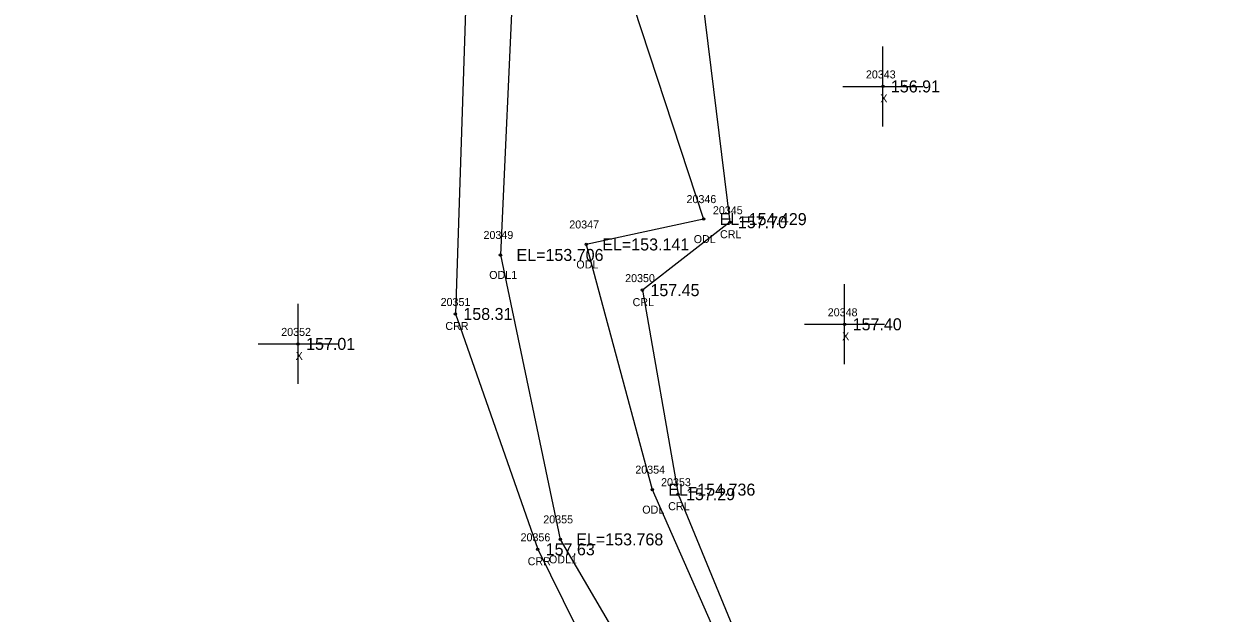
# Model space of a CAD drawing. Extents: x 2381545 to 2382928, y 1029933 to 1030589.
# Drawn here: x 2382160.7 to 2382309.6, y 1030240.2 to 1030313.9 of the extents above; entities that cross this region are included whole.
import ezdxf

# ---------------------------------------------------------------- set-up
doc = ezdxf.new("R2010")
doc.units = 0
for name, color, linetype in [('RD_EX_H2O', 7, 'Continuous'), ('RD_EX_H2O_txCode', 7, 'Continuous'), ('RD_EX_Misc', 7, 'Continuous'), ('RD_EX_Misc_txCode', 7, 'Continuous'), ('RD_EX_TX_H2O_ELEV', 7, 'Continuous'), ('RD_EX_TX_Misc_ELEV', 7, 'Continuous'), ('RD_SMD_Locator', 7, 'Continuous')]:
    doc.layers.add(name, color=color, linetype=linetype)

msp = doc.modelspace()

# ---------------------------------------------------------------- linework, layer by layer
at = {"layer": 'RD_EX_H2O'}
for points in [[(2382228.76, 1030407.08), (2382229.33, 1030393.42), (2382229.44, 1030376.02), (2382235.1, 1030355.5), (2382240.51, 1030349.49), (2382245.56, 1030316.86), (2382248.97, 1030289.05), (2382238.04, 1030280.56), (2382242.49, 1030255.05), (2382259.38, 1030214.05), (2382335.14, 1030213.97), (2382351.43, 1030124.97), (2382330.65, 1030084.53), (2382333.22, 1030050.31), (2382344.99, 1030019.27), (2382333.68, 1029961.92)], [(2382160.73, 1030399.39), (2382197.66, 1030393.98), (2382201.16, 1030391.22), (2382207.75, 1030374.4), (2382216.83, 1030343.34), (2382214.66, 1030277.58), (2382224.95, 1030248.16), (2382253.35, 1030190.66), (2382280.97, 1030189.84), (2382308.61, 1030179.94), (2382336.27, 1030122.7), (2382320.51, 1030086.69), (2382321.43, 1030050.4), (2382332.53, 1030017.35), (2382333.68, 1029961.92)], [(2382220.88, 1030388.74), (2382227.06, 1030360.93), (2382229.81, 1030345.11), (2382235.02, 1030321.93), (2382245.69, 1030289.44), (2382231.02, 1030286.27), (2382239.27, 1030255.62), (2382259.54, 1030209.53), (2382328.62, 1030208.08), (2382346.92, 1030124.75), (2382326.86, 1030085.52), (2382331.57, 1030050.13), (2382343.53, 1030018.97), (2382333.68, 1029961.92)], [(2382213.26, 1030387.6), (2382221.81, 1030359.48), (2382223.97, 1030346.38), (2382221.92, 1030320.69), (2382220.3, 1030284.96), (2382227.77, 1030249.4), (2382256.92, 1030199.53), (2382280.94, 1030192.97), (2382312.22, 1030183.5), (2382338.65, 1030122.69), (2382323.29, 1030086.32), (2382328.28, 1030050.33), (2382335.32, 1030017.57), (2382333.68, 1029961.92)]]:
    msp.add_lwpolyline(points, dxfattribs=at)
at = {"layer": 'RD_EX_Misc'}
for p, q in [((2382268.09, 1030301.03), (2382268.09, 1030311.03)), ((2382263.09, 1030306.03), (2382273.09, 1030306.03)), ((2382263.31, 1030271.29), (2382263.31, 1030281.29)), ((2382195.01, 1030268.84), (2382195.01, 1030278.84)), ((2382258.31, 1030276.29), (2382268.31, 1030276.29)), ((2382190.01, 1030273.84), (2382200.01, 1030273.84))]:
    msp.add_line(p, q, dxfattribs=at)
at = {"layer": 'RD_SMD_Locator'}
for centre in [(2382268.09, 1030306.03), (2382245.69, 1030289.44), (2382248.97, 1030289.05), (2382220.3, 1030284.96), (2382231.02, 1030286.27), (2382238.04, 1030280.56), (2382214.66, 1030277.58), (2382263.31, 1030276.29), (2382195.01, 1030273.84), (2382239.27, 1030255.62), (2382242.49, 1030255.05), (2382227.77, 1030249.4), (2382224.95, 1030248.16)]:
    msp.add_circle(centre, 0.15, dxfattribs=at)

# ---------------------------------------------------------------- texts
at = {"layer": 'RD_EX_H2O_txCode'}
for s, p in [('20346', (2382243.55, 1030291.44)), ('20345', (2382246.85, 1030290.05)), ('20349', (2382218.18, 1030286.96)), ('20347', (2382228.9, 1030288.27)), ('CRL', (2382247.74, 1030287.05)), ('ODL', (2382244.45, 1030286.44)), ('ODL', (2382229.78, 1030283.27)), ('ODL1', (2382218.89, 1030281.96)), ('20350', (2382235.88, 1030281.56)), ('20351', (2382212.82, 1030278.58)), ('CRL', (2382236.81, 1030278.56)), ('CRR', (2382213.41, 1030275.58)), ('20354', (2382237.15, 1030257.62)), ('20353', (2382240.37, 1030256.05)), ('CRL', (2382241.26, 1030253.05)), ('20355', (2382225.65, 1030251.4)), ('ODL', (2382238.02, 1030252.62)), ('20356', (2382222.81, 1030249.16)), ('CRR', (2382223.7, 1030246.16)), ('ODL1', (2382226.36, 1030246.4))]:
    msp.add_text(s, height=1, dxfattribs=at).set_placement(p)
at = {"layer": 'RD_EX_Misc_txCode'}
for s, p in [('20343', (2382265.97, 1030307.03)), ('X', (2382267.77, 1030304.03)), ('20348', (2382261.2, 1030277.29)), ('20352', (2382192.9, 1030274.84)), ('X', (2382263, 1030274.29)), ('X', (2382194.7, 1030271.84))]:
    msp.add_text(s, height=1, dxfattribs=at).set_placement(p)
at = {"layer": 'RD_EX_TX_H2O_ELEV'}
for s, p in [('EL=154.429', (2382247.69, 1030288.69)), ('157.70', (2382249.97, 1030288.3)), ('EL=153.141', (2382233.02, 1030285.52)), ('EL=153.706', (2382222.3, 1030284.21)), ('157.45', (2382239.04, 1030279.81)), ('158.31', (2382215.66, 1030276.83)), ('EL=154.736', (2382241.27, 1030254.87)), ('157.29', (2382243.49, 1030254.3)), ('EL=153.768', (2382229.77, 1030248.65)), ('157.63', (2382225.95, 1030247.41))]:
    msp.add_text(s, height=1.5, dxfattribs=at).set_placement(p)
at = {"layer": 'RD_EX_TX_Misc_ELEV'}
for s, p in [('156.91', (2382269.09, 1030305.28)), ('157.40', (2382264.31, 1030275.54)), ('157.01', (2382196.01, 1030273.09))]:
    msp.add_text(s, height=1.5, dxfattribs=at).set_placement(p)

doc.saveas('drawing.dxf')
